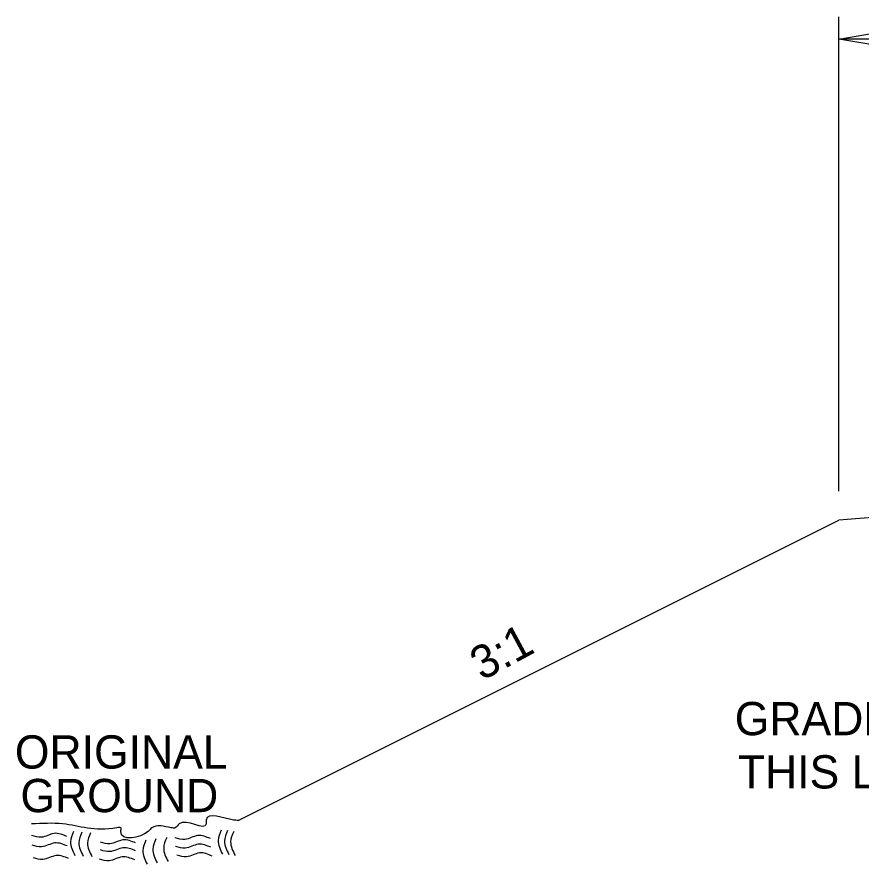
# Model space of a CAD drawing. Extents: x 1593595 to 1594166, y 741647 to 741854.
# Drawn here: x 1594030.72 to 1594051.46, y 741764.4 to 741785.23 of the extents above; entities that cross this region are included whole.
import ezdxf

# ---------------------------------------------------------------- set-up
doc = ezdxf.new("R2010")
doc.units = 0
for name, color, linetype in [('Old_Level_1', 7, 'Continuous'), ('Old_Level_11', 7, 'Continuous'), ('Old_Level_2', 7, 'Continuous'), ('Old_Level_3', 7, 'Continuous'), ('Prop Terminator CELL', 7, 'Continuous')]:
    doc.layers.add(name, color=color, linetype=linetype)

msp = doc.modelspace()

# ---------------------------------------------------------------- linework, layer by layer
at = {"layer": 'Old_Level_1'}
for p in [(1594056.925, 741773.331), (1594036.155, 741765.469)]:
    msp.add_line(p, (1594050.92, 741772.851), dxfattribs=at)
at = {"layer": 'Old_Level_11'}
for p, q in [((1594050.92, 741773.564), (1594050.92, 741785.225)), ((1594058.92, 741784.68), (1594050.92, 741784.68))]:
    msp.add_line(p, q, dxfattribs=at)
at = {"layer": 'Old_Level_2'}
for points in [[(1594036.155, 741765.469), (1594036.042, 741765.481), (1594035.373, 741765.481), (1594035.373, 741765.385), (1594034.705, 741765.385), (1594034.61, 741765.29), (1594034.514, 741765.29), (1594034.037, 741765.29), (1594033.942, 741765.195), (1594033.274, 741765.195), (1594033.274, 741765.29), (1594033.178, 741765.29), (1594031.842, 741765.385), (1594031.081, 741765.385)], [(1594035.737, 741765.232), (1594035.662, 741764.975), (1594035.769, 741764.644)], [(1594035.897, 741765.221), (1594035.822, 741764.965), (1594035.929, 741764.633)], [(1594031.947, 741765.077), (1594031.637, 741765.152), (1594031.316, 741765.056), (1594031.081, 741765.098)], [(1594032.113, 741765.2), (1594032.038, 741764.943), (1594032.145, 741764.612)], [(1594032.316, 741765.178), (1594032.241, 741764.922), (1594032.348, 741764.59)], [(1594032.53, 741765.168), (1594032.455, 741764.911), (1594032.562, 741764.58)], [(1594033.636, 741764.916), (1594033.326, 741764.991), (1594033.005, 741764.895), (1594032.77, 741764.938)], [(1594034.133, 741765.018), (1594034.058, 741764.762), (1594034.165, 741764.43)], [(1594034.4, 741765.05), (1594034.326, 741764.794), (1594034.433, 741764.462)], [(1594035.475, 741765.023), (1594035.165, 741765.098), (1594034.844, 741765.002), (1594034.609, 741765.045)], [(1594036.047, 741765.2), (1594035.972, 741764.943), (1594036.079, 741764.612)], [(1594031.958, 741764.842), (1594031.648, 741764.916), (1594031.327, 741764.82), (1594031.092, 741764.863)], [(1594033.636, 741764.724), (1594033.326, 741764.799), (1594033.005, 741764.703), (1594032.77, 741764.745)], [(1594033.887, 741764.986), (1594033.813, 741764.729), (1594033.919, 741764.398)], [(1594035.486, 741764.81), (1594035.176, 741764.884), (1594034.855, 741764.788), (1594034.62, 741764.831)], [(1594031.99, 741764.532), (1594031.68, 741764.606), (1594031.359, 741764.51), (1594031.124, 741764.553)], [(1594033.615, 741764.5), (1594033.305, 741764.574), (1594032.984, 741764.478), (1594032.749, 741764.521)], [(1594035.518, 741764.596), (1594035.208, 741764.671), (1594034.887, 741764.574), (1594034.652, 741764.617)]]:
    msp.add_spline(points, degree=3, dxfattribs=at)
at = {"layer": 'Prop Terminator CELL'}
msp.add_lwpolyline([(1594051.902, 741784.511), (1594050.92, 741784.68), (1594051.907, 741784.854), (1594051.782, 741784.68)], close=True, dxfattribs=at)

# ---------------------------------------------------------------- texts
at = {"layer": 'Old_Level_1'}
for s, p in [('GRADE TO ', (1594048.359, 741767.565)), ('ORIGINAL', (1594030.669, 741766.745)), ('THIS LINE', (1594048.436, 741766.256)), ('GROUND', (1594030.806, 741765.673))]:
    msp.add_text(s, height=0.8181, dxfattribs=at).set_placement(p)
at = {"layer": 'Old_Level_3'}
msp.add_text('3:1', height=0.8181, rotation=28.3904, dxfattribs=at).set_placement((1594042.148, 741768.894))

doc.saveas('drawing.dxf')
